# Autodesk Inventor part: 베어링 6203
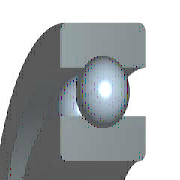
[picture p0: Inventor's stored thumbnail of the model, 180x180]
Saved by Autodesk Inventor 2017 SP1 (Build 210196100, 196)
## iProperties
IsCustomPart: 0
Created: 2018-09
Part Number: 베어링 6203
Material: 스테인리스강
Description: 깊은 그루브 볼 베어링
Document SubType Name: Modeling
Standard: KS B 2023
Standards Organization: KS
Language: ko-KR
Size Designation: 6203 - 17 x 40 x 12
Categories: <MemberInstance><Categories><Category DisplayName="샤프트 부품" InternalName="7f7aeb1f-a693-4053-b835-cee3144e0d98" Mnemonic="SHFT"><Category DisplayName="베어링" Inter
Density: 8.08 g/cm^3
Mass: 66.7997 g
Surface Area: 64.3582 cm^2
Volume: 8.26729 cm^3
Appearance: 보라색
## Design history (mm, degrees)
sketch "스케치" dims "d0" = 5.98 (= -0.26 x WD + 0.26 x BD)
  geometry: L1 (3.01, 14.25)-(8.99, 14.25); L2 (6, 14.25)-(6, 11.26); L3 (6, 14.25)-(6, 17.24); L4 (3.778, 12.249)-(0, 12.249); L5 (0, 8.5)-(12, 8.5); L6 (3.778, 16.251)-(0, 16.251); L7 (0, 20)-(12, 20); L8 (12, 8.5)-(12, 12.249); L9 (8.222, 12.249)-(12, 12.249); L10 (8.222, 16.251)-(12, 16.251); L11 (12, 20)-(12, 16.251); L12 (-1.4, 0)-(8.4, 0) reference; L13 (0, -0.3)-(0, 5.3) reference
  constraints: 22 end point, 4 point on line, 2 collinear, 2 perpendicular, 2 symmetric about line, 1 midpoint, 1 parallel, 14 other
  dimensions: "d9" = 17 diameter of L5 L12 (= WD); "d11" = 40 diameter of L7 L12 (= BD); "d12" = 12 distance between parallel lines of L8 L13 (= KB); "d13" = 24.498 diameter of L9 L12 (= 0.326 x BD + 0.674 x WD)
revolve "본체" stored, may be unused: angle "d6" = 90 deg
revolve "볼" stored, may be unused: angle "d7" = 90 deg
pattern_circular "IDS_ARRAYBALL[SIMPL:T]" dims angle "d3" = 360 deg
body "Solid1"
fillet "모깎기1" dims "d1" = 0.6 (= KRS)
other parameters: "WD" = 17 [user parameter; used in 5 equation terms], "BD" = 40 [user parameter; used in 5 equation terms], "KB" = 12 [user parameter; used in 1 equation term], "KRS" = 0.6 [user parameter; used in 1 equation term], "d4" = 0, "d5" = 0, "d8" = 0, "d14" = 0, "d15" = 0, "BBA" = 0 [user parameter], "BC0" = 4750000 [user parameter], "BC" = 9560000 [user parameter], "WR" = 8.5 (= 0.5 x WD) [user parameter]
